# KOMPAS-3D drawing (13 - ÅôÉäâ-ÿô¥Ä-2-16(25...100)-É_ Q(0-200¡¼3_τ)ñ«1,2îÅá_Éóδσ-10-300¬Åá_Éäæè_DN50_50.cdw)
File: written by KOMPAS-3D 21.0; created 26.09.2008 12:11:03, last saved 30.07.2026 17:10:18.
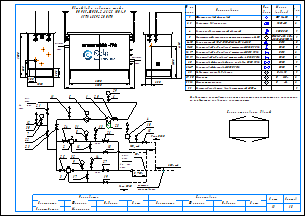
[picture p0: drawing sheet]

Sheets 1-2: A3, landscape

Document properties: Наименование: Макро:21; Автор: RaskoAdmin; Форматы листов документа: 2xA3; Полное имя файла: \\ur38nt01\Departments\КТО\КБ ПУРДГ\Заявки\Прайс-лист на типовые шкафы ГРПШ\ПУРДГ_стандарт_30_04_2026\ПУРДГ с РДСК\ПУРДГ-ШУЭО-2-16(25...100)-Р_ Q(0-200нм3_ч)до1,2МПа_Рвых-10-300кПа_РДСК_DN50_50.cdw

Title block, sheet 1: Наименование: Пункт учета газа / ПУГ-Ш-400-Р / ЛГТИ.485922.001ТУ; designation: ЛГТИ.03.4411141; sheet number: 1; Количество листов документа: 2; organisation: ООО "ЭЛЬСТЕР Газэлектроника"; Форматы листов документа: A3; stored path: C:\Рабочие документы\Компас\ПУГ\Схема.cdw; Разработал: Устинов; Проверил: Кошкин; Утвердил: Кошкин
Title block, sheet 2: sheet number: 2; stored path: D:\Рабочие документы\Заявки\ПУРДГ\ПУРДГ-ШУЭО-2-100-Р 4411220.cdw; designation, second copy: ЛГТИ.03.4411141-

Views: Вид 1, Вид 2
Referenced files: wcvoit.frw
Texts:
  Normal
  № на
  схеме
  Усл.
  обозн.
  Марка
  (модель)
  Кол.
  Фильтр газовый фланцевый
  ФГ 16-50
  Регулятор давления газа
  РДСК-50
  Клапан предохранительный сбросной
  КПС DN20
  Измерительный комплекс с ротационным счетчиком Ду50
  СГ-ЭК-Р-(0,2...2,0)-
  Кран кнопочный VE-РАСКО-НЗ-1,6-G1/2-М20
  DN15
  Кран шаровой "под приварку" штуцерный DN20 PN16
  DN20
  Кран шаровой "под приварку" штуцерный DN15 PN16
  Кран шаровой "под приварку" штуцерный п/п DN20 PN16
  Кран шаровой фланцевый с мех. приводом DN50 PN16
  Кран шаровой фланцевый DN50 PN16
  DN50
  Индикатор перепада давления
  Манометр
  Манометр-напоромер
  Электрообогреватель взрывозащищенный 400Вт
  Delta 15
  0...     МПа
  0...     кПа
  Общий вид и габариты шкафа
  ПУРДГ-ШУЭО-2-16(25...100)-Р
  Выход газа
  Вход газа
  logo-rasko-ge.png
  DN 1
  местное
  сопротивление
  Римп DN20
  Выход
  газа
  Р=     кПа
  Вход
  Р=       МПа
  PDI
  Схема открывания дверей
  Предприятие изготовитель может заменять комплектующие на аналогичные,
  не ухудшающие заявленных характеристик.
  Должность
  Конструктор
  Фамилия
  Подпись
  Дата
  Согласовано
  Максимкин
  Лист
  Листов
  POLYLINE_STYLE_0.18_RGB_0_0_0
  POLYLINE_STYLE_0.50_RGB_0_0_0
  POLYLINE_STYLE_0.34_RGB_0_0_0
  PHANTOM_RGB_0_0_0_SC_1_THICK_0.18
  K5LT_THIN_RGB_0_0_0_THICK_0.18
  K5LT32769_RGB_0_0_0_THICK_0.18
  K5LT12_RGB_0_0_0_SC_1_THICK_0.18
  K5LT_DASHED_RGB_0_0_0_SC_1_THICK_0.18
  ACISOTGL_RGB_0_0_0_SC_0.8_THICK_0.25
  CONTINUOUS_RGB_0_127_31_THICK_0.3
  CONTINUOUS_RGB_0_0_255_THICK_0.35
  CONTINUOUS_RGB_255_0_0_THICK_0.35
  POLYLINE_STYLE_0.25_RGB_0_0_0
  CONTINUOUS_RGB_0_0_0_THICK_0.5
  POLYLINE_STYLE_0.35_RGB_0_0_255
  CONTINUOUS_RGB_0_0_0_THICK_0.4
  CONTINUOUS_RGB_0_0_0_THICK_0.35
  НЕВИДИМАЯ_RGB_0_0_0_SC_0.3_THICK_0.25
  СONTINUOUS_RGB_0_0_0_THICK_0.25
  ОСЕВАЯ2_RGB_248_153_30_SC_0.3_THICK_0.25
  Без оформления
Dimensions and other numbers on the sheet: 1; 2, 3; 2; 4; 5; 6-10; 11-15; 16, 17; 18, 19; 20; 21-27; 7; 28; 29, 30; 31, 32; 33; 1500; 250; 300; 1050; 550; 305; 2000; 4130; 2300; 5,,,7DN 1; 30; 12; 21; 22; 23; 11; 6; 29; 24; 31; 8; 16; 13; 26; 18; 10; 15; 25; 32; 9; 3; 17; 14; 27; 19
